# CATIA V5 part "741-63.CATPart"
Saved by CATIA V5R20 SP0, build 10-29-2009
Part number: 741-63
Bounding box of the stored display mesh (mm): x -47.5 to 47.5, y -47.5 to 47.5, z -60 to 56
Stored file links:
  C:\Users\Utente\Desktop\IO LAVORO\3D X SITO CF\X SITO\741\741-63.CATPart
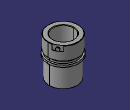
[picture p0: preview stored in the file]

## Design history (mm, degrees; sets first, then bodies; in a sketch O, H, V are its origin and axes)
Set1
  DatumSurface1 to DatumSurface42 "741-63"
Body1 (main body)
